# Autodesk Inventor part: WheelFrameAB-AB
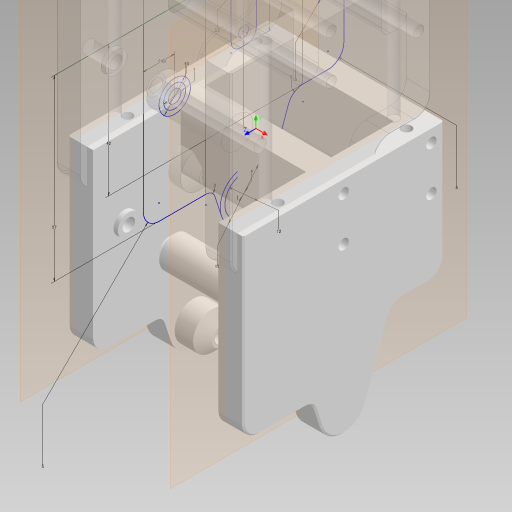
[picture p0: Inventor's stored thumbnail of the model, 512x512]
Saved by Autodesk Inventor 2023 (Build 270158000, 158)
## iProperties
Created: 2024-05
Part Number: WheelFrameAB-AB
Material: 一般
Document SubType Name: Modeling
Designer: kumagai
Density: 1 g/cm^3
Appearance: 既定
Author: kumagai
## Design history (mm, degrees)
derived "WheelFrameAB.ipt"
feature "ソリッド1::WheelFrameAB.ipt"
tag "TaggingFeature1"
node "ソリッド1"
other parameters: "d1" = 4, "d2" = 4, "d3" = 42, "d4" = 5, "d5" = 15, "d6" = 5, "d7" = 57, "d8" = 5, "d9" = 3, "d10" = 32, "d11" = 5, "d13" = 12, "d14" = 32, "d16" = 5, "d17" = 8, "d18" = 22, "d19" = 8, "d20" = 22, "d21" = 4, "d22" = 4, "d23" = 3.3, "d24" = 8, "d26" = 8, "d28" = 3.2, "d30" = 0, "d31" = 8.9, "d33" = 13.4, "d35" = 3, "d39" = 7, "d40" = 1.4, "d42" = 2, "d45" = 25.9, "d47" = 25.9, "d68" = 54.8, "d69" = 0, "d70" = 3, "d71" = 0.5
